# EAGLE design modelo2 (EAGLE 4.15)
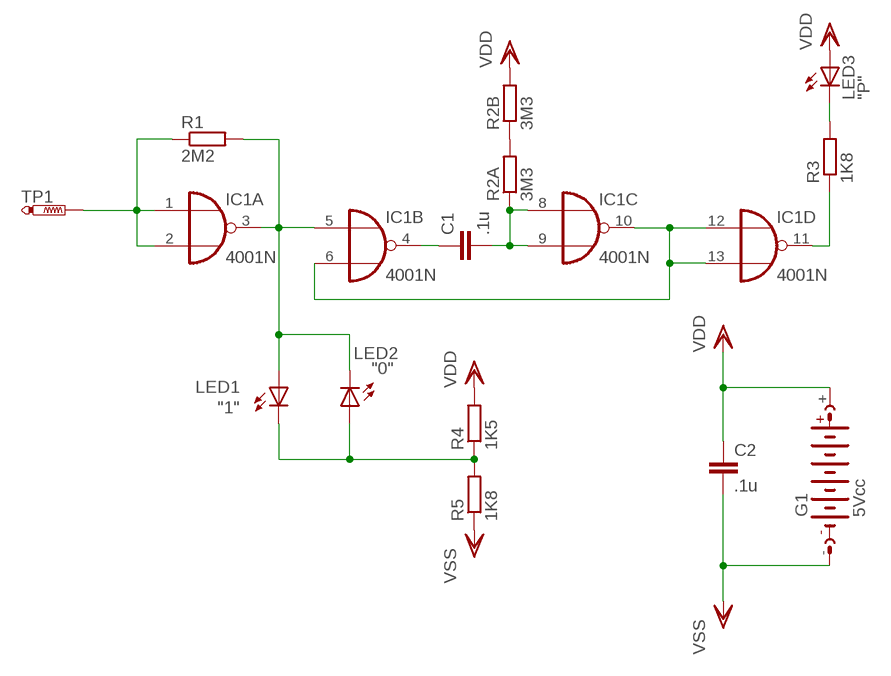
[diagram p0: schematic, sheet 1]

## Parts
C1  .1u  C-EU050-030X075  [C050-030X075]
C2  .1u  C-EU050-030X075  [C050-030X075]
G1  5Vcc  AB9V  [AB9V]
IC1  4001N  [DIL14]
LED1  "1"  LED3MM  [LED3MM]
LED2  "0"  LED3MM  [LED3MM]
LED3  "P"  LED3MM  [LED3MM]
R1  2M2  R-EU_0204/7  [0204/7]
R2A  3M3  R-EU_0204/7  [0204/7]
R2B  3M3  R-EU_0204/7  [0204/7]
R3  1K8  R-EU_0204/7  [0204/7]
R4  1K5  R-EU_0204/7  [0204/7]
R5  1K8  R-EU_0204/7  [0204/7]
TP1  PTR1PAD1-17  [P1-17]

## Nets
N$2: IC1.3(A:O) IC1.5(B:I0) LED1.A LED2.K(C) R1.2
N$5: LED1.K(C) LED2.A R4.1 R5.2
N$7: LED3.K(C) R3.2
N$8: IC1.11(D:O) R3.1
N$9: C1.1 IC1.4(B:O)
N$10: C1.2 IC1.8(C:I0) IC1.9(C:I1) R2A.1
N$11: IC1.6(B:I1) IC1.10(C:O) IC1.12(D:I0) IC1.13(D:I1)
N$13: R2A.2 R2B.1
TIP: IC1.1(A:I0) IC1.2(A:I1) R1.1 TP1.1(TP)
VDD: C2.1 G1.+ LED3.A R2B.2 R4.2
VSS: C2.2 G1.- R5.1

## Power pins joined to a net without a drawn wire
VDD: IC1.14(P:VDD)
VSS: IC1.7(P:VSS)

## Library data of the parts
C1 C2 = rcl:C-EU: CAPACITOR, European symbol
G1 = battery:AB9V: 9-V BATTERY CLIP
IC1 = 40xx:4001: Quad 2-input NOR
LED1-LED3 = led:LED: LED
R1 R2A R2B R3-R5 = rcl:R-EU_: RESISTOR, European symbol
TP1 = testpad:PTR1: TEST PIN

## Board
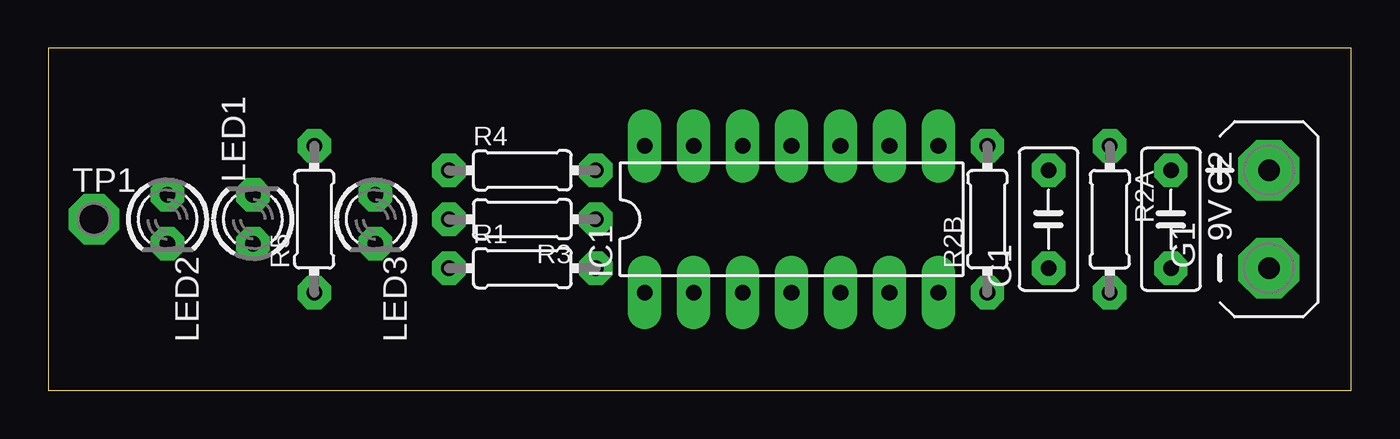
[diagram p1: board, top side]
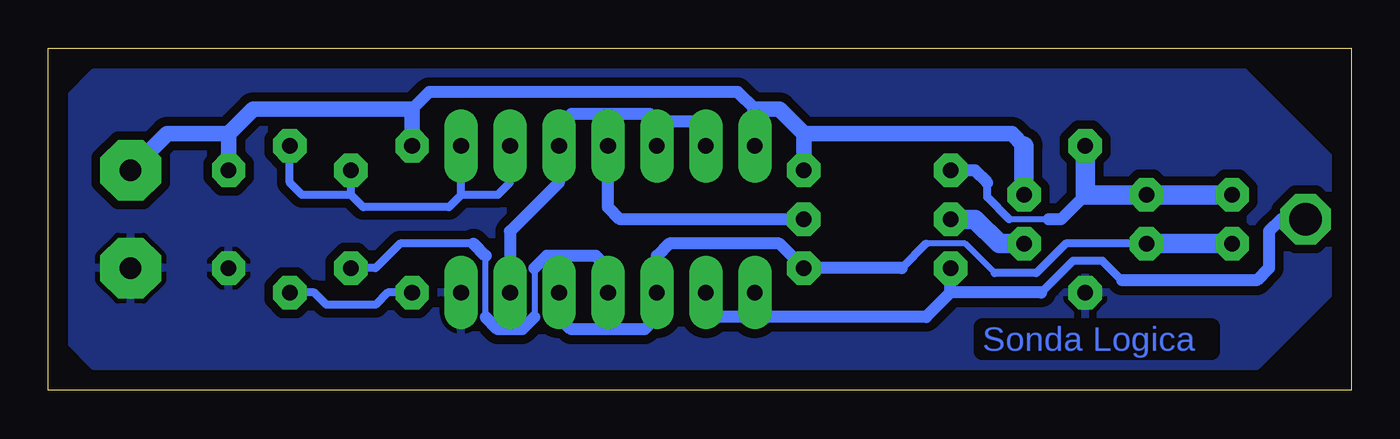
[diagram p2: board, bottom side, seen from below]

Size 67.61 x 17.77 mm. Coordinates in mm from the lower left corner, seen from the top.
Outline: 0,0 67.61,0 67.61,17.77 0,17.77 0,0
Copper layers (1*16): Top 0.035mm / dielectric 1.5mm / Bottom 0.035mm
Design rules "redondo": minimum track width 10mil, minimum drill 3mil, track to track 18mil, track to pad 18mil, pad to pad 18mil, via to via 18mil, smd to smd 8mil, copper to edge 40mil, drill to drill 8mil, minimum pad ring 18mil, minimum via ring 8mil, stop-mask expansion 4mil, vias tented up to drill 0mil, thermal gap 10mil

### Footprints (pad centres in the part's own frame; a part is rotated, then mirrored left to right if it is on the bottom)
C050-030X075 = drill 0.813 octagon: 1 -2.54,0; 2 2.54,0
AB9V = drill 1.118 pad 3.15 octagon: + 0,2.54; - 0,-2.54
DIL14 = drill 0.813 long: 1 -7.62,-3.81; 2 -5.08,-3.81; 3 -2.54,-3.81; 4 0,-3.81; 5 2.54,-3.81; 6 5.08,-3.81; 7 7.62,-3.81; 8 7.62,3.81; 9 5.08,3.81; 10 2.54,3.81; 11 0,3.81; 12 -2.54,3.81; 13 -5.08,3.81; 14 -7.62,3.81
LED3MM = drill 0.813 octagon: A -1.27,0; K 1.27,0
0204/7 = drill 0.813 octagon: 1 -3.81,0; 2 3.81,0
P1-17 = drill 1.702 pad 2.54 octagon: 1 0,0

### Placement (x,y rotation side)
C1  51.91,8.89 90 top
C2  58.25,8.89 270 top
G1  63.34,8.89 0 top
IC1  38.57,8.89 0 top
LED1  10.63,8.89 90 top
LED2  6.18,8.89 270 top
LED3  16.98,8.89 270 top
R1  24.6,6.34 0 top
R2A  55.08,8.89 270 top
R2B  48.73,8.89 90 top
R3  24.6,8.89 180 top
R4  24.6,11.43 0 top
R5  13.81,8.89 90 top
TP1  2.38,8.89 0 top

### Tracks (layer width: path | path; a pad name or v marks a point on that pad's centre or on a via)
N$2
  Bottom 0.305: 22.06,7.62 20.03,7.62 18.5,6.09
  Bottom 0.406: 22.06,7.62 23.33,6.34 | 18.5,6.09 16.34,6.09 14.82,7.62 LED1.A
  Bottom 0.61: IC1.5 41.11,3.8 40.48,3.17 36.66,3.17 36.03,3.8 IC1.3 36.03,6.98 35.39,7.62 29.68,7.62 R1.2 23.33,6.34
  Bottom 1.016: LED2.K LED1.A
N$5
  Bottom 0.305: 15.71,8.89 17.74,8.89
  Bottom 0.406: 17.74,8.89 18.88,10.03 18.88,10.79
  Bottom 0.61: 13.81,10.16 15.08,8.89 15.71,8.89 | R4.1 19.52,11.43 18.88,10.79
  Bottom 1.016: LED2.A LED1.K 13.81,10.16 R5.2
N$7
  Bottom 1.016: R3.2 19.52,8.89 18.25,7.62 LED3.K
N$8
  Bottom 0.61: R3.1 37.94,8.89 38.57,9.52 IC1.11
N$9
  Bottom 0.305: 44.92,3.8 44.92,6.98 | 42.38,6.34 42.38,3.8
  Bottom 0.406: C1.1 50.63,6.34 49.37,7.62 45.55,7.62
  Bottom 0.61: 44.92,6.98 45.55,7.62 | 44.92,3.8 44.28,3.17 43.02,3.17 42.38,3.8 | 42.38,6.34 41.74,6.98 39.2,6.98 38.57,6.34 IC1.4
N$10
  Bottom 0.406: 46.19,10.16 IC1.8 | 46.19,10.16 44.28,10.16 43.65,10.79 IC1.9 | R2A.1 55.08,10.79 54.45,10.16 51.91,10.16 | 51.91,10.16 C1.2 | 46.19,10.16 46.82,9.52 51.27,9.52 51.91,10.16
N$11
  Bottom 0.61: 36.03,13.97 36.41,14.35 40.48,14.35 41.11,13.71 IC1.10 41.11,10.79 43.65,8.25 IC1.6 | IC1.13 33.49,13.58 33.87,13.97 36.03,13.97 | 36.03,13.97 IC1.12
N$13
  Bottom 0.406: R2B.1 50,5.08 50.63,4.44 53.17,4.44 53.81,5.08 R2A.2
TIP  (via drill 0.5 pad 2.54)
  Bottom 0.406: 11.9,5.71 12.92,6.73 14.44,6.73 16.09,5.08 | 30.95,4.44 IC1.1
  Bottom 0.61: IC1.2 33.49,4.44 32.85,3.8 31.58,3.8 30.95,4.44 30.31,3.8 22.06,3.8 20.79,5.08 | TP1.1 3.64,8.89 4.28,8.25 4.28,6.34 4.92,5.71 11.9,5.71 | 16.09,5.08 20.79,5.08 | 20.79,5.08 R1.1
  other vias: 2.38,8.89
VDD
  Bottom 0.61: 48.73,14.6 47.84,15.49 31.84,15.49 30.95,14.6
  Bottom 0.813: G1.+ 61.43,13.33 58.25,13.33 | 58.25,13.33 C2.1 | R2B.2 48.73,14.6 56.98,14.6 58.25,13.33 | IC1.14 30.95,14.6 29.68,14.6 28.41,13.33 | 28.41,13.33 R4.2 | 16.98,12.7 17.61,13.33 28.41,13.33
  Bottom 1.016: LED3.A 16.98,12.7
VSS
  pour Bottom: 0.47,5.71 0.47,11.43 5.55,16.5 65.24,16.5 66.51,15.24 66.51,2.54 65.24,1.27 4.92,1.27

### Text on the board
Bottom: Sonda Logica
